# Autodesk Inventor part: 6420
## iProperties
Author: Ole Germer
Shininess: 64.0
Angle Display Precision: 2
Document Length Units: 11272
Document Angle Units: 11286
Document Time Units: 11279
Document Mass Units: 11290
Document Length Units Precision: 3
Document Angle Units Precision: 2
Compacted: True
PropertySet Name: _Private Model Information
Created: 2002-10
Part Number: 6420
Material: Steel, High Strength Low Alloy
Document SubType Name: Modeling
Designer: Ole Germer
Control State: 0
Master: False
Checked Out: False
PropertySet Name: Design Tracking Control
Density: 0.0
Volumn: 0.0
Area: 0.0
PropertySet Name: Model Information
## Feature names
1. Revolution1
